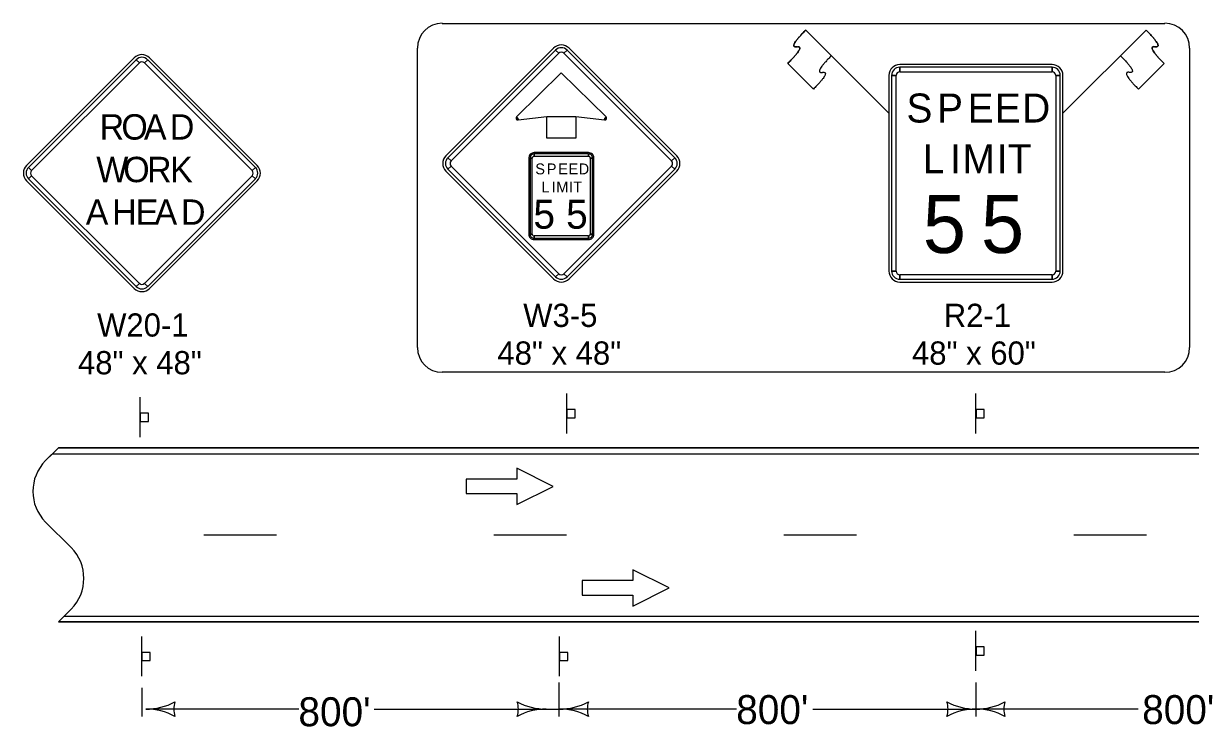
# Model space of a CAD drawing. Extents: x 10133 to 2270741, y 5363 to 1733450.
# Drawn here: x 28131 to 28936, y 6604 to 7089 of the extents above; entities that cross this region are included whole.
import ezdxf

# ---------------------------------------------------------------- set-up
doc = ezdxf.new("R2010")
doc.units = 0
for name, color, linetype in [('dsnNonPlotable', 7, 'Continuous'), ('dsnStdBorder', 7, 'Continuous'), ('Level 12', 7, 'Continuous'), ('Level 2', 7, 'Continuous')]:
    doc.layers.add(name, color=color, linetype=linetype)

msp = doc.modelspace()

# ---------------------------------------------------------------- linework, layer by layer
at = {"layer": 'dsnNonPlotable'}
for p, q in [((28154.78, 6795.83), (28146, 6787.04)), ((28146, 6744.62), (28163.56, 6727.05)), ((28163.56, 6684.63), (28154.78, 6675.84)), ((28158.76, 6679.83), (29774.05, 6679.83))]:
    msp.add_line(p, q, dxfattribs=at)
for points in [[(28150.78, 6791.83), (30180.37, 6791.83)], [(28255.15, 6735.82), (28305.15, 6735.82)], [(28455.12, 6735.82), (28505.12, 6735.82)], [(28655.09, 6735.82), (28705.08, 6735.82)], [(28855.06, 6735.82), (28905.05, 6735.82)]]:
    msp.add_lwpolyline(points, dxfattribs=at)
for centre, start, end in [((28167.2, 6765.83), 135, 225), ((28142.36, 6705.84), 315, 45)]:
    msp.add_arc(centre, 30, start, end, dxfattribs=at)
at = {"layer": 'dsnStdBorder'}
for p, q in [((28727.46, 7026.69), (28670.14, 7084.01)), ((28670.14, 7084.01), (28687.83, 7066.32)), ((28847.46, 7026.69), (28904.78, 7084.01)), ((28904.78, 7084.01), (28887.09, 7066.32)), ((28496.28, 7071.54), (28422.03, 6997.29)), ((28497.6, 7070.21), (28499.81, 7068)), ((28503.35, 7068), (28505.56, 7070.21)), ((28581.13, 6997.29), (28506.88, 7071.54)), ((28207.08, 7064.89), (28132.83, 6990.64)), ((28208.4, 7063.56), (28210.61, 7061.35)), ((28214.15, 7061.35), (28216.36, 7063.56)), ((28291.93, 6990.64), (28217.68, 7064.89)), ((28657.77, 7061.02), (28675.44, 7043.34)), ((28675.44, 7043.34), (28657.77, 7061.02)), ((28839.96, 7060.24), (28734.96, 7060.24)), ((28917.16, 7061.02), (28899.48, 7043.34)), ((28899.48, 7043.34), (28917.16, 7061.02)), ((28727.46, 7052.74), (28727.46, 6917.74)), ((28729.34, 7052.74), (28732.46, 7052.74)), ((28734.96, 7055.24), (28734.96, 7058.37)), ((28839.96, 7058.37), (28839.96, 7055.24)), ((28842.46, 7052.74), (28845.59, 7052.74)), ((28847.46, 6917.74), (28847.46, 7052.74)), ((28471.58, 7023.24), (28470.7, 7024.12)), ((28471.74, 7022), (28471.58, 7023.24)), ((28531.58, 7023.24), (28531.43, 7022)), ((28532.46, 7024.12), (28531.58, 7023.24)), ((28425.57, 6993.75), (28423.36, 6995.96)), ((28479.08, 6995.74), (28479.08, 6943.24)), ((28480.02, 6995.74), (28481.58, 6995.74)), ((28520.33, 6999.49), (28482.83, 6999.49)), ((28482.83, 6996.99), (28482.83, 6998.55)), ((28520.33, 6998.55), (28520.33, 6996.99)), ((28521.58, 6995.74), (28523.14, 6995.74)), ((28524.08, 6943.24), (28524.08, 6995.74)), ((28579.8, 6995.96), (28577.59, 6993.75)), ((28136.36, 6987.1), (28134.16, 6989.31)), ((28290.6, 6989.31), (28288.39, 6987.1)), ((28422.03, 6986.68), (28496.28, 6912.44)), ((28423.36, 6988.01), (28425.57, 6990.22)), ((28506.88, 6912.44), (28581.13, 6986.68)), ((28577.59, 6990.22), (28579.8, 6988.01)), ((28132.83, 6980.03), (28207.08, 6905.79)), ((28134.16, 6981.36), (28136.36, 6983.57)), ((28217.68, 6905.79), (28291.93, 6980.03)), ((28288.39, 6983.57), (28290.6, 6981.36)), ((28481.58, 6943.24), (28480.02, 6943.24)), ((28482.83, 6940.43), (28482.83, 6941.99)), ((28482.83, 6939.49), (28520.33, 6939.49)), ((28520.33, 6941.99), (28520.33, 6940.43)), ((28523.14, 6943.24), (28521.58, 6943.24)), ((28499.81, 6915.97), (28497.6, 6913.76)), ((28505.56, 6913.76), (28503.35, 6915.97)), ((28732.46, 6917.74), (28729.34, 6917.74)), ((28734.96, 6912.12), (28734.96, 6915.24)), ((28839.96, 6915.24), (28839.96, 6912.12)), ((28845.59, 6917.74), (28842.46, 6917.74)), ((28210.61, 6909.32), (28208.4, 6907.11)), ((28216.36, 6907.11), (28214.15, 6909.32)), ((28734.96, 6910.24), (28839.96, 6910.24)), ((28211.12, 6803.3), (28211.12, 6830.8)), ((28505.37, 6805.83), (28505.37, 6833.33)), ((28787.46, 6805.83), (28787.46, 6833.33)), ((28212.32, 6638.33), (28212.32, 6665.83)), ((28500.26, 6638.33), (28500.26, 6665.83)), ((28787.48, 6642.06), (28787.48, 6669.56))]:
    msp.add_line(p, q, dxfattribs=at)
for points in [[(28419.4, 7088.64), (28917.8, 7088.64)], [(28402.37, 6864.98), (28402.37, 7071.62)], [(28934.82, 7071.62), (28934.82, 6864.98)], [(28917.8, 6847.95), (28419.4, 6847.95)], [(28435.86, 6774.26), (28435.86, 6764.26), (28470.86, 6764.26), (28470.86, 6756.76), (28495.86, 6769.26), (28470.86, 6781.76), (28470.86, 6774.26), (28435.86, 6774.26)], [(28515.85, 6704.27), (28515.85, 6694.27), (28550.85, 6694.27), (28550.85, 6686.77), (28575.85, 6699.27), (28550.85, 6711.77), (28550.85, 6704.27), (28515.85, 6704.27)]]:
    msp.add_lwpolyline(points, dxfattribs=at)
for points in [[(28497.6, 7070.21), (28423.36, 6995.96), (28425.57, 6993.75), (28499.81, 7068), (28497.6, 7070.21)], [(28579.8, 6995.96), (28505.56, 7070.21), (28503.35, 7068), (28577.59, 6993.75), (28579.8, 6995.96)], [(28208.4, 7063.56), (28134.16, 6989.31), (28136.36, 6987.1), (28210.61, 7061.35), (28208.4, 7063.56)], [(28290.6, 6989.31), (28216.36, 7063.56), (28214.15, 7061.35), (28288.39, 6987.1), (28290.6, 6989.31)], [(28501.58, 7054.49), (28470.7, 7024.12), (28471.58, 7023.24), (28471.74, 7022), (28491.58, 7024.49), (28511.58, 7024.49), (28531.43, 7022), (28531.58, 7023.24), (28532.46, 7024.12), (28501.58, 7054.49)], [(28729.34, 7052.74), (28729.34, 6917.74), (28732.46, 6917.74), (28732.46, 7052.74), (28729.34, 7052.74)], [(28839.96, 7058.37), (28734.96, 7058.37), (28734.96, 7055.24), (28839.96, 7055.24), (28839.96, 7058.37)], [(28845.59, 6917.74), (28845.59, 7052.74), (28842.46, 7052.74), (28842.46, 6917.74), (28845.59, 6917.74)], [(28511.58, 7009.49), (28491.58, 7009.49), (28491.58, 7024.49), (28511.58, 7024.49), (28511.58, 7009.49)], [(28480.02, 6995.74), (28480.02, 6943.24), (28481.58, 6943.24), (28481.58, 6995.74), (28480.02, 6995.74)], [(28520.33, 6998.55), (28482.83, 6998.55), (28482.83, 6996.99), (28520.33, 6996.99), (28520.33, 6998.55)], [(28523.14, 6943.24), (28523.14, 6995.74), (28521.58, 6995.74), (28521.58, 6943.24), (28523.14, 6943.24)], [(28423.36, 6988.01), (28497.6, 6913.76), (28499.81, 6915.97), (28425.57, 6990.22), (28423.36, 6988.01)], [(28505.56, 6913.76), (28579.8, 6988.01), (28577.59, 6990.22), (28503.35, 6915.97), (28505.56, 6913.76)], [(28134.16, 6981.36), (28208.4, 6907.11), (28210.61, 6909.32), (28136.36, 6983.57), (28134.16, 6981.36)], [(28216.36, 6907.11), (28290.6, 6981.36), (28288.39, 6983.57), (28214.15, 6909.32), (28216.36, 6907.11)], [(28482.83, 6940.43), (28520.33, 6940.43), (28520.33, 6941.99), (28482.83, 6941.99), (28482.83, 6940.43)], [(28734.96, 6912.12), (28839.96, 6912.12), (28839.96, 6915.24), (28734.96, 6915.24), (28734.96, 6912.12)], [(28211.21, 6819.75), (28211.21, 6814.12), (28216.84, 6814.12), (28216.84, 6819.75)], [(28505.47, 6822.27), (28505.47, 6816.65), (28511.09, 6816.65), (28511.09, 6822.27)], [(28787.56, 6822.27), (28787.56, 6816.65), (28793.18, 6816.65), (28793.18, 6822.27)], [(28787.57, 6658.51), (28787.57, 6652.88), (28793.2, 6652.88), (28793.2, 6658.51)], [(28212.42, 6654.77), (28212.42, 6649.15), (28218.04, 6649.15), (28218.04, 6654.77)], [(28500.36, 6654.77), (28500.36, 6649.15), (28505.98, 6649.15), (28505.98, 6654.77)]]:
    msp.add_lwpolyline(points, close=True, dxfattribs=at)
for centre, radius, start, end in [((28419.4, 7071.62), 17.03, 90, 180), ((28917.8, 7071.62), 17.03, 0, 90), ((28212.38, 7059.58), 7.5, 44.99999, 134.99974), ((28501.58, 7066.23), 7.5, 44.99999, 134.99974), ((28501.58, 7066.23), 5.62, 44.99999, 134.99974), ((28501.58, 7066.23), 2.5, 44.99999, 134.99974), ((28212.38, 7059.58), 5.62, 44.99999, 134.99974), ((28212.38, 7059.58), 2.5, 44.99999, 134.99974), ((28734.96, 7052.74), 7.5, 90.00021, 179.99985), ((28839.96, 7052.74), 7.5, 0, 90.00021), ((28734.96, 7052.74), 5.62, 90.00021, 179.99985), ((28734.96, 7052.74), 2.5, 90.00021, 179.99985), ((28839.96, 7052.74), 5.62, 0, 90.00021), ((28839.96, 7052.74), 2.5, 0, 90.00021), ((28471.58, 7023.24), 1.25, 134.99974, 277.15286), ((28531.58, 7023.24), 1.25, 262.84725, 44.9998), ((28427.33, 6991.99), 7.5, 134.99974, 224.99995), ((28427.33, 6991.99), 5.62, 134.99974, 224.99995), ((28482.83, 6995.74), 3.75, 90.00021, 179.99985), ((28482.83, 6995.74), 2.81, 90.00021, 179.99985), ((28482.83, 6995.74), 1.25, 90.00021, 179.99985), ((28520.33, 6995.74), 3.75, 0, 90.00021), ((28520.33, 6995.74), 2.81, 0, 90.00021), ((28520.33, 6995.74), 1.25, 0, 90.00021), ((28575.83, 6991.99), 5.62, 315.00016, 44.9998), ((28575.83, 6991.99), 7.5, 315.00016, 44.9998), ((28138.13, 6985.34), 7.5, 134.99974, 224.99995), ((28138.13, 6985.34), 5.62, 134.99974, 224.99995), ((28138.13, 6985.34), 2.5, 134.99974, 224.99995), ((28286.62, 6985.34), 2.5, 315.00016, 44.9998), ((28286.62, 6985.34), 5.62, 315.00016, 44.9998), ((28286.62, 6985.34), 7.5, 315.00016, 44.9998), ((28427.33, 6991.99), 2.5, 134.99974, 224.99995), ((28575.83, 6991.99), 2.5, 315.00016, 44.9998), ((28482.83, 6943.24), 3.75, 179.99985, 270.00006), ((28482.83, 6943.24), 2.81, 179.99985, 270.00006), ((28482.83, 6943.24), 1.25, 179.99985, 270.00006), ((28520.33, 6943.24), 3.75, 270.00006, 0.00027), ((28520.33, 6943.24), 2.81, 270.00006, 0.00027), ((28520.33, 6943.24), 1.25, 270.00006, 0.00027), ((28501.58, 6917.74), 2.5, 224.99995, 315.00016), ((28734.96, 6917.74), 7.5, 179.99985, 270.00006), ((28734.96, 6917.74), 5.62, 179.99985, 270.00006), ((28734.96, 6917.74), 2.5, 179.99985, 270.00006), ((28839.96, 6917.74), 7.5, 270.00006, 0.00027), ((28839.96, 6917.74), 5.62, 270.00006, 0.00027), ((28839.96, 6917.74), 2.5, 270.00006, 0.00027), ((28212.38, 6911.09), 5.62, 224.99995, 315.00016), ((28212.38, 6911.09), 2.5, 224.99995, 315.00016), ((28501.58, 6917.74), 7.5, 224.99995, 315.00016), ((28501.58, 6917.74), 5.62, 224.99995, 315.00016), ((28212.38, 6911.09), 7.5, 224.99995, 315.00016), ((28419.4, 6864.98), 17.03, 180, 270), ((28917.8, 6864.98), 17.03, 270, 0)]:
    msp.add_arc(centre, radius, start, end, dxfattribs=at)
for points in [[(28670.14, 7084.01), (28657.77, 7071.62), (28670.14, 7073.39), (28657.77, 7061.02)], [(28657.77, 7061.02), (28670.14, 7073.39), (28657.77, 7071.62), (28670.14, 7084.01)], [(28904.78, 7084.01), (28917.16, 7071.62), (28904.78, 7073.39), (28917.16, 7061.02)], [(28917.16, 7061.02), (28904.78, 7073.39), (28917.16, 7071.62), (28904.78, 7084.01)], [(28687.83, 7066.32), (28675.45, 7053.94), (28687.82, 7055.71), (28675.44, 7043.34)], [(28687.83, 7066.32), (28675.45, 7053.94), (28687.82, 7055.71), (28675.44, 7043.34)], [(28887.09, 7066.32), (28899.48, 7053.94), (28887.11, 7055.71), (28899.48, 7043.34)], [(28887.09, 7066.32), (28899.48, 7053.94), (28887.11, 7055.71), (28899.48, 7043.34)]]:
    msp.add_open_spline(points, degree=2, dxfattribs=at)
at = {"layer": 'Level 12'}
for p, q in [((28499.88, 6634.06), (28499.88, 6610.59)), ((28787.48, 6634.06), (28787.48, 6610.59)), ((28212.32, 6630.33), (28212.32, 6610.59)), ((28787.46, 6630.33), (28787.46, 6610.59)), ((28320.52, 6615.65), (28215.12, 6615.65)), ((28372.45, 6615.65), (28499.88, 6615.65)), ((28622.33, 6615.65), (28499.88, 6615.65)), ((28675.02, 6615.65), (28787.48, 6615.65)), ((28899.26, 6615.65), (28787.48, 6615.65))]:
    msp.add_line(p, q, dxfattribs=at)
for centre, radius, start, end in [((28215.12, 6658.15), 42.5, 270, 298.07249), ((28250.76, 6615.65), 16.42, 162.26665, 197.73335), ((28455.53, 6615.65), 16.42, 342.26665, 17.73335), ((28491.17, 6658.15), 42.5, 241.92751, 270), ((28500.26, 6658.15), 42.5, 270, 298.07249), ((28535.9, 6615.65), 16.42, 162.26665, 197.73335), ((28751.83, 6615.65), 16.42, 342.26665, 17.73335), ((28787.46, 6658.15), 42.5, 241.92751, 270), ((28787.46, 6658.15), 42.5, 270, 298.07249), ((28823.1, 6615.65), 16.42, 162.26665, 197.73335), ((28215.12, 6573.15), 42.5, 61.92751, 90), ((28491.17, 6573.15), 42.5, 90, 118.07249), ((28500.26, 6573.15), 42.5, 61.92751, 90), ((28787.46, 6573.15), 42.5, 90, 118.07249), ((28787.46, 6573.15), 42.5, 61.92751, 90)]:
    msp.add_arc(centre, radius, start, end, dxfattribs=at)
at = {"layer": 'Level 2'}
for p, q in [((28154.78, 6795.83), (28150.78, 6791.83)), ((29944.62, 6795.82), (28154.78, 6795.83)), ((28154.78, 6795.82), (30281.4, 6795.82)), ((28145.99, 6787.04), (28150.78, 6791.83)), ((28150.78, 6791.83), (29368.02, 6791.83)), ((28150.78, 6791.83), (29946.34, 6791.83)), ((28163.57, 6727.05), (28145.99, 6744.62)), ((28154.78, 6675.83), (28163.57, 6684.63)), ((28154.78, 6675.83), (30486.98, 6675.83)), ((29199.26, 6675.83), (28154.78, 6675.83))]:
    msp.add_line(p, q, dxfattribs=at)
msp.add_lwpolyline([(28150.78, 6791.83), (28150.78, 6791.83)], dxfattribs=at)
msp.add_lwpolyline([(28150.78, 6791.83), (28150.78, 6791.83)], dxfattribs=at)
for centre, start, end in [((28167.2, 6765.83), 135, 225), ((28142.36, 6705.84), 315, 45)]:
    msp.add_arc(centre, 30, start, end, dxfattribs=at)

# ---------------------------------------------------------------- texts
at = {"layer": 'dsnStdBorder'}
for s, height, p in [('S', 20, (28739.59, 7020.24)), ('P', 20, (28760.68, 7020.24)), ('E', 20, (28781.78, 7020.24)), ('E', 20, (28800.58, 7020.24)), ('D', 20, (28819.39, 7020.24)), ('R', 17.5, (28183.22, 7008.46)), ('O', 17.5, (28198.23, 7008.46)), ('A', 17.5, (28213.78, 7008.46)), ('D', 17.5, (28231.66, 7008.46)), ('L', 20, (28750.84, 6985.24)), ('I', 20, (28769.65, 6985.24)), ('M', 20, (28778.24, 6985.24)), ('I', 20, (28801.83, 6985.24)), ('T', 20, (28809.39, 6985.24)), ('W', 17.5, (28180.93, 6979.09)), ('O', 17.5, (28199.53, 6979.09)), ('R', 17.5, (28215.93, 6979.09)), ('K', 17.5, (28231.79, 6979.09)), ('S', 7.5, (28483.63, 6984.49)), ('P', 7.5, (28491.54, 6984.49)), ('E', 7.5, (28499.45, 6984.49)), ('E', 7.5, (28506.5, 6984.49)), ('D', 7.5, (28513.56, 6984.49)), ('L', 7.5, (28487.85, 6971.99)), ('I', 7.5, (28494.9, 6971.99)), ('M', 7.5, (28498.12, 6971.99)), ('I', 7.5, (28506.97, 6971.99)), ('T', 7.5, (28509.81, 6971.99)), ('A', 17.5, (28173.66, 6949.71)), ('H', 17.5, (28191.86, 6949.71)), ('E', 17.5, (28208.09, 6949.71)), ('A', 17.5, (28221.14, 6949.71)), ('D', 17.5, (28239.34, 6949.71)), ('5', 20, (28482.33, 6946.99)), ('5', 20, (28504.89, 6946.99)), ('5', 40, (28750.84, 6930.24)), ('5', 40, (28790.96, 6930.24)), ('W3-5', 16, (28475.33, 6879.24)), ('R2-1', 16, (28765.3, 6879.24)), ('W20-1', 16, (28181.52, 6872.59)), ('48" x 48"', 16, (28457.51, 6853.24)), ('48" x 60"', 16, (28743.39, 6853.24)), ('48" x 48"', 16, (28168.31, 6846.59))]:
    msp.add_text(s, height=height, dxfattribs=at).set_placement(p)
at = {"layer": 'Level 12'}
for p in [(28622.18, 6605.32), (28902.09, 6605.32), (28320.3, 6603.83)]:
    msp.add_text("800'", height=20, dxfattribs=at).set_placement(p)

doc.saveas('drawing.dxf')
